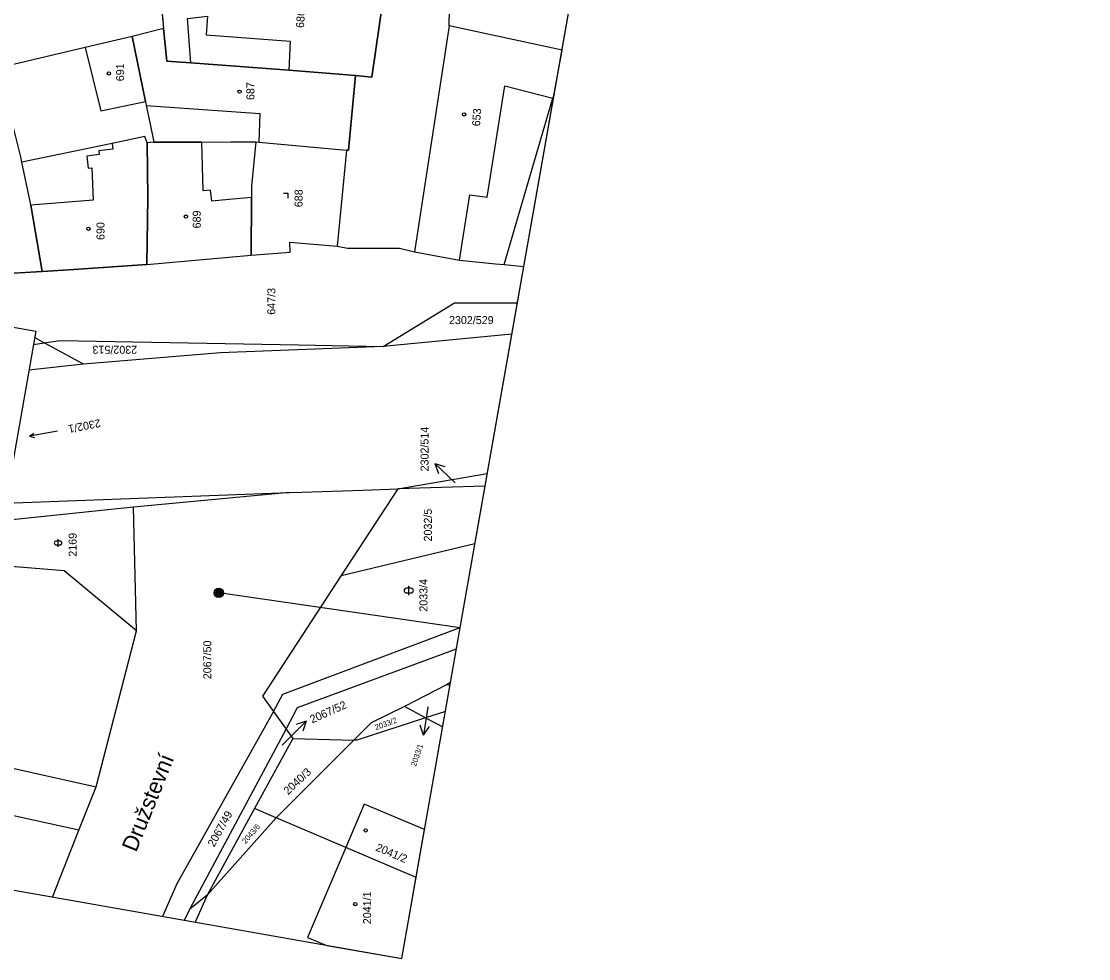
# Model space of a CAD drawing. Extents: x -534481 to -534256, y -1190577 to -1190138.
# Drawn here: x -534375 to -534261.7, y -1190577.1 to -1190477.6 of the extents above; entities that cross this region are included whole.
import ezdxf

# ---------------------------------------------------------------- set-up
doc = ezdxf.new("R2010")
doc.units = 0
for name, color, linetype in [('_N_text', 7, 'Continuous'), ('_rámeček', 7, 'Continuous'), ('_rámeček_mřížka', 7, 'Continuous'), ('Hranice parcel', 7, 'Continuous'), ('Parcelní čísla', 7, 'Continuous'), ('Polygon budovy', 7, 'Continuous'), ('Pop  PČ popisy', 7, 'Continuous'), ('Poz předměty', 7, 'Continuous'), ('Značky budov', 7, 'Continuous'), ('Značky kultur', 7, 'Continuous')]:
    doc.layers.add(name, color=color, linetype=linetype)

msp = doc.modelspace()

# ---------------------------------------------------------------- linework, layer by layer
at = {"layer": '_N_text'}
msp.add_lwpolyline([(-534383.28, -1190540.32), (-534377.88, -1190509.67), (-534373.46, -1190510.44), (-534378.87, -1190541.1)], close=True, dxfattribs=at)
at = {"layer": '_rámeček'}
for points in [[(-534407.91, -1190137.67), (-534480.84, -1190551.29), (-534334.6, -1190577.08), (-534261.67, -1190163.46)], [(-534480.84, -1190551.29), (-534334.6, -1190577.08), (-534316.37, -1190473.68)]]:
    msp.add_lwpolyline(points, dxfattribs=at)
at = {"layer": '_rámeček_mřížka'}
msp.add_lwpolyline([(-534480.84, -1190551.29), (-534334.6, -1190577.08), (-534261.67, -1190163.46)], dxfattribs=at)
at = {"layer": 'Hranice parcel'}
for p, q in [((-534360.35, -1190473.34), (-534359.92, -1190478.31)), ((-534359.92, -1190478.31), (-534363.23, -1190479.17)), ((-534329.58, -1190478.02), (-534333.24, -1190502.03)), ((-534317.59, -1190480.63), (-534329.58, -1190478.02)), ((-534323.74, -1190503.39), (-534318.55, -1190485.72)), ((-534318.55, -1190485.72), (-534318.46, -1190485.43)), ((-534318.41, -1190485.26), (-534318.46, -1190485.43)), ((-534360.94, -1190490.38), (-534361.64, -1190490.44)), ((-534365.36, -1190490.52), (-534374.94, -1190492.52)), ((-534340.49, -1190491.25), (-534341.45, -1190501.42)), ((-534374.94, -1190492.52), (-534375.06, -1190491.94)), ((-534323.74, -1190503.39), (-534321.64, -1190503.57)), ((-534372.8, -1190504.12), (-534384.53, -1190504.78)), ((-534373.71, -1190511.86), (-534372.58, -1190511.69)), ((-534368.41, -1190513.97), (-534372.58, -1190511.69)), ((-534346.53, -1190527.59), (-534363.09, -1190529.14)), ((-534335.01, -1190527.19), (-534341.03, -1190536.4)), ((-534362.76, -1190542.27), (-534363.09, -1190529.14)), ((-534341.03, -1190536.4), (-534326.83, -1190533.01)), ((-534341.03, -1190536.4), (-534349.4, -1190549.21)), ((-534367.07, -1190558.85), (-534362.76, -1190542.27)), ((-534329.84, -1190547.99), (-534334.33, -1190550.31)), ((-534329.49, -1190548.07), (-534329.84, -1190547.99)), ((-534349.4, -1190549.21), (-534348.24, -1190550.82)), ((-534332.09, -1190551.51), (-534334.33, -1190550.31)), ((-534348.24, -1190550.82), (-534346.89, -1190552.7)), ((-534329.97, -1190550.83), (-534332.09, -1190551.51)), ((-534332.09, -1190551.51), (-534330.26, -1190552.46)), ((-534357.1, -1190571.82), (-534346.89, -1190552.7)), ((-534346.89, -1190552.7), (-534346.17, -1190553.69)), ((-534346.17, -1190553.69), (-534350.25, -1190561.15)), ((-534339.7, -1190553.88), (-534347.95, -1190562.13)), ((-534346.17, -1190553.69), (-534339.7, -1190553.88)), ((-534368.89, -1190563.45), (-534367.07, -1190558.85)), ((-534350.25, -1190561.15), (-534355.26, -1190570.33)), ((-534347.95, -1190562.13), (-534350.25, -1190561.15)), ((-534347.95, -1190562.13), (-534355.26, -1190570.33)), ((-534340.55, -1190565.28), (-534347.95, -1190562.13)), ((-534371.69, -1190570.54), (-534368.89, -1190563.45)), ((-534333.08, -1190568.46), (-534340.55, -1190565.28)), ((-534355.26, -1190570.33), (-534357.1, -1190571.82)), ((-534355.26, -1190570.33), (-534356.54, -1190573.21)), ((-534357.68, -1190573.01), (-534357.1, -1190571.82))]:
    msp.add_line(p, q, dxfattribs=at)
for points in [[(-534329.58, -1190478.02), (-534329.52, -1190476.22), (-534329.36, -1190471.67), (-534329.3, -1190469.99)], [(-534336.54, -1190474.87), (-534337.79, -1190483.49), (-534339.53, -1190483.31)], [(-534359.92, -1190478.31), (-534359.56, -1190481.78), (-534357.01, -1190481.97), (-534346.59, -1190482.73), (-534339.53, -1190483.31)], [(-534363.23, -1190479.17), (-534368.22, -1190480.34), (-534375.83, -1190482.13)], [(-534363.23, -1190479.17), (-534361.82, -1190486.07), (-534361.73, -1190486.49), (-534361.36, -1190488.3), (-534360.94, -1190490.38)], [(-534339.53, -1190483.31), (-534340.26, -1190491.25), (-534340.49, -1190491.25)], [(-534318.46, -1190485.43), (-534318.44, -1190485.44)], [(-534361.64, -1190490.44), (-534361.87, -1190489.79), (-534365.36, -1190490.52)], [(-534360.94, -1190490.38), (-534357.12, -1190490.37), (-534355.82, -1190490.37), (-534352.77, -1190490.36), (-534350.1, -1190490.36)], [(-534350.1, -1190490.36), (-534350.56, -1190495.07), (-534350.57, -1190496.27), (-534350.6, -1190502.38)], [(-534350.1, -1190490.36), (-534349.79, -1190490.39), (-534340.49, -1190491.25)], [(-534361.64, -1190490.44), (-534361.58, -1190496.28), (-534361.66, -1190503.37)], [(-534372.8, -1190504.12), (-534374.01, -1190497.07), (-534374.08, -1190496.69), (-534374.94, -1190492.52)], [(-534350.6, -1190502.38), (-534346.45, -1190502.08), (-534346.49, -1190501), (-534341.45, -1190501.42)], [(-534341.45, -1190501.42), (-534340.38, -1190501.64), (-534334.84, -1190501.63), (-534333.24, -1190502.03)], [(-534361.66, -1190503.37), (-534355.33, -1190502.8), (-534350.6, -1190502.38)], [(-534333.24, -1190502.03), (-534328.48, -1190502.91), (-534324.65, -1190503.31), (-534323.74, -1190503.39)], [(-534361.66, -1190503.37), (-534369.42, -1190503.89), (-534372.8, -1190504.12)], [(-534336.58, -1190512.09), (-534329.01, -1190507.46), (-534322.32, -1190507.44)], [(-534322.91, -1190510.76), (-534336.58, -1190512.09)], [(-534373.58, -1190511.14), (-534372.58, -1190511.69)], [(-534372.58, -1190511.69), (-534370.92, -1190511.44), (-534345.58, -1190511.92), (-534336.58, -1190512.09)], [(-534336.58, -1190512.09), (-534353.84, -1190512.76), (-534368.41, -1190513.97)], [(-534368.41, -1190513.97), (-534374.19, -1190514.59)], [(-534335.01, -1190527.19), (-534325.52, -1190525.55)], [(-534376.68, -1190528.73), (-534346.53, -1190527.59)], [(-534346.53, -1190527.59), (-534345.23, -1190527.54), (-534338.73, -1190527.32), (-534335.01, -1190527.19)], [(-534325.76, -1190526.92), (-534335.01, -1190527.19)], [(-534363.09, -1190529.14), (-534377.01, -1190530.6)], [(-534362.76, -1190542.27), (-534370.46, -1190535.9), (-534377.84, -1190535.3)], [(-534348.24, -1190550.82), (-534347.22, -1190548.99), (-534328.4, -1190541.93)], [(-534346.89, -1190552.7), (-534345.66, -1190550.4), (-534328.8, -1190544.19)], [(-534329.43, -1190547.76), (-534329.84, -1190547.99)], [(-534334.33, -1190550.31), (-534337.86, -1190552.04), (-534339.7, -1190553.88)], [(-534348.24, -1190550.82), (-534358.48, -1190569.12), (-534360.01, -1190572.6)], [(-534332.09, -1190551.51), (-534339.39, -1190553.89), (-534339.7, -1190553.88)], [(-534393.95, -1190555.65), (-534390.54, -1190553.66), (-534381.04, -1190555.72), (-534367.07, -1190558.85)], [(-534368.89, -1190563.45), (-534382.12, -1190560.55), (-534386.52, -1190559.61), (-534386.17, -1190557.95), (-534389.54, -1190557.26), (-534390.5, -1190557.91), (-534393.95, -1190555.65)], [(-534332.18, -1190563.36), (-534338.6, -1190560.69), (-534340.55, -1190565.28)], [(-534340.55, -1190565.28), (-534344.61, -1190574.82), (-534342.56, -1190575.68)]]:
    msp.add_lwpolyline(points, dxfattribs=at)
at = {"layer": 'Polygon budovy'}
msp.add_line((-534318.41, -1190485.26), (-534317.59, -1190480.63), dxfattribs=at)
for points in [[(-534360.35, -1190473.34), (-534359.92, -1190478.31), (-534359.56, -1190481.78), (-534357.01, -1190481.97), (-534357.36, -1190477.25), (-534355.22, -1190476.99), (-534355.37, -1190478.98), (-534346.45, -1190479.65), (-534346.59, -1190482.73), (-534339.53, -1190483.31), (-534337.79, -1190483.49), (-534336.54, -1190474.87), (-534344.1, -1190474.27), (-534347.75, -1190473.84), (-534350.15, -1190473.56), (-534350.19, -1190473.9)], [(-534361.82, -1190486.07), (-534361.73, -1190486.49), (-534349.66, -1190487.33), (-534349.79, -1190490.39), (-534340.49, -1190491.25), (-534340.26, -1190491.25), (-534339.53, -1190483.31), (-534346.59, -1190482.73), (-534357.01, -1190481.97), (-534359.56, -1190481.78), (-534359.92, -1190478.31), (-534363.23, -1190479.17)], [(-534368.22, -1190480.34), (-534366.57, -1190487.06), (-534361.82, -1190486.07), (-534363.23, -1190479.17)], [(-534381.11, -1190486.74), (-534379.63, -1190494.14), (-534379.04, -1190497.06), (-534379.33, -1190497.08), (-534385.97, -1190497.46), (-534389.82, -1190497.69), (-534389.86, -1190498.78), (-534389.63, -1190505.06), (-534385.13, -1190504.81), (-534384.53, -1190504.78), (-534372.8, -1190504.12), (-534374.01, -1190497.07), (-534374.08, -1190496.69), (-534374.94, -1190492.52), (-534375.06, -1190491.94), (-534376.48, -1190486.28), (-534380.38, -1190486.72)], [(-534361.87, -1190489.79), (-534365.36, -1190490.52), (-534365.27, -1190491.11), (-534366.77, -1190491.32), (-534366.72, -1190491.69), (-534368.03, -1190491.87), (-534367.89, -1190493.13), (-534367.51, -1190493.1), (-534367.39, -1190496.53), (-534374.01, -1190497.07), (-534372.8, -1190504.12), (-534369.42, -1190503.89), (-534361.66, -1190503.37), (-534361.58, -1190496.28), (-534361.64, -1190490.44)], [(-534361.66, -1190503.37), (-534355.33, -1190502.8), (-534350.6, -1190502.38), (-534350.57, -1190496.27), (-534352.95, -1190496.47), (-534354.79, -1190496.64), (-534354.9, -1190495.48), (-534355.71, -1190495.55), (-534355.82, -1190490.37), (-534357.12, -1190490.37), (-534360.94, -1190490.38), (-534361.64, -1190490.44), (-534361.58, -1190496.28)]]:
    msp.add_lwpolyline(points, close=True, dxfattribs=at)
for points in [[(-534317.59, -1190480.63), (-534329.58, -1190478.02), (-534333.24, -1190502.03), (-534328.48, -1190502.91), (-534327.37, -1190495.99), (-534325.53, -1190496.23), (-534323.67, -1190484.39), (-534318.55, -1190485.72), (-534318.46, -1190485.43), (-534318.41, -1190485.26)], [(-534332.18, -1190563.36), (-534338.6, -1190560.69), (-534340.55, -1190565.28), (-534344.61, -1190574.82), (-534342.56, -1190575.68)], [(-534342.56, -1190575.68), (-534334.6, -1190577.08), (-534332.18, -1190563.36)]]:
    msp.add_lwpolyline(points, dxfattribs=at)
at = {"layer": 'Pop  PČ popisy'}
for p, q in [((-534328.92, -1190526.56), (-534331.11, -1190524.51)), ((-534331.11, -1190524.51), (-534330.03, -1190524.83)), ((-534331.11, -1190524.51), (-534330.72, -1190525.56)), ((-534331.83, -1190550.39), (-534332.3, -1190553.35)), ((-534331.82, -1190550.33), (-534331.83, -1190550.39)), ((-534346.89, -1190553.97), (-534344.77, -1190551.85)), ((-534344.77, -1190551.85), (-534345.83, -1190552.2)), ((-534344.77, -1190551.85), (-534345.12, -1190552.91)), ((-534332.3, -1190553.35), (-534332.64, -1190552.29)), ((-534332.3, -1190553.35), (-534331.65, -1190552.44)), ((-534347.32, -1190554.4), (-534346.89, -1190553.97))]:
    msp.add_line(p, q, dxfattribs=at)
at = {"layer": 'Poz předměty'}
msp.add_line((-534328.41, -1190541.97), (-534354.04, -1190538.24), dxfattribs=at)
for radius in [0.5, 0.4, 0.3, 0.2, 0.1]:
    msp.add_circle((-534354.04, -1190538.24), radius, dxfattribs=at)
at = {"layer": 'Značky budov'}
for centre in [(-534365.7, -1190483.09), (-534351.83, -1190485.02), (-534327.99, -1190487.44), (-534357.53, -1190498.29), (-534367.88, -1190499.57), (-534338.44, -1190563.47), (-534339.55, -1190571.29)]:
    msp.add_circle(centre, 0.175, dxfattribs=at)
at = {"layer": 'Značky kultur'}
for p, q in [((-534346.67, -1190495.83), (-534347.17, -1190495.83)), ((-534346.67, -1190496.33), (-534346.67, -1190495.83)), ((-534371.17, -1190521.08), (-534374.13, -1190521.6)), ((-534374.13, -1190521.6), (-534373.69, -1190521.27)), ((-534374.13, -1190521.6), (-534373.6, -1190521.76)), ((-534370.9, -1190532.74), (-534371.3, -1190532.74)), ((-534371.3, -1190533.14), (-534370.9, -1190533.14)), ((-534371.1, -1190533.34), (-534371.1, -1190532.54)), ((-534333.61, -1190537.75), (-534334.11, -1190537.75)), ((-534333.86, -1190538.5), (-534333.86, -1190537.5)), ((-534334.11, -1190538.25), (-534333.61, -1190538.25))]:
    msp.add_line(p, q, dxfattribs=at)
for centre, radius, start, end in [((-534371.3, -1190532.94), 0.2, 90, 270), ((-534370.9, -1190532.94), 0.2, 270, 89.9879), ((-534334.11, -1190538), 0.25, 90, 270), ((-534333.61, -1190538), 0.25, 270, 89.9879)]:
    msp.add_arc(centre, radius, start, end, dxfattribs=at)

# ---------------------------------------------------------------- texts
at = {"layer": 'Parcelní čísla'}
for s, height, rotation, p in [('686', 0.85, 86, (-534345, -1190478.28)), ('691', 0.85, 90, (-534364.09, -1190483.91)), ('687', 0.85, 90, (-534350.25, -1190485.91)), ('653', 0.85, 86, (-534326.3, -1190488.72)), ('688', 0.85, 90, (-534345.14, -1190497.29)), ('689', 0.85, 90, (-534355.95, -1190499.54)), ('690', 0.85, 90, (-534366.17, -1190500.77)), ('647/3', 0.85, 90, (-534348.03, -1190508.71)), ('2302/513', 0.85, 180, (-534362.7, -1190512)), ('2302/1', 0.85, 191, (-534366.67, -1190519.78)), ('2302/514', 0.85, 90, (-534331.76, -1190525.34)), ('2032/5', 0.85, 90, (-534331.41, -1190532.78)), ('2169', 0.85, 90, (-534369.13, -1190534.4)), ('2033/4', 0.85, 90, (-534331.88, -1190540.24)), ('2067/50', 0.85, 90, (-534354.83, -1190547.41)), ('2067/52', 0.85, 24, (-534344.13, -1190552.11)), ('2033/2', 0.595, 19.8461, (-534337.34, -1190552.83)), ('2033/1', 0.595, 71, (-534333.1, -1190556.71)), ('2040/3', 0.85, 43, (-534346.68, -1190559.73)), ('2067/49', 0.85, 61, (-534354.53, -1190565.29)), ('2043/6', 0.595, 49.4126, (-534351.18, -1190564.94)), ('2041/2', 0.85, 337, (-534337.45, -1190565.58)), ('2041/1', 0.85, 90, (-534337.86, -1190573.42))]:
    msp.add_text(s, height=height, rotation=rotation, dxfattribs=at).set_placement(p)
msp.add_text('2302/529', height=0.85, dxfattribs=at).set_placement((-534329.59, -1190509.7))
at = {"layer": 'Pop  PČ popisy'}
msp.add_text('Družstevní', height=1.7, rotation=68, dxfattribs=at).set_placement((-534362.81, -1190565.85))

doc.saveas('drawing.dxf')
